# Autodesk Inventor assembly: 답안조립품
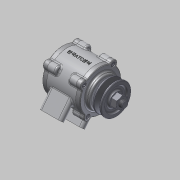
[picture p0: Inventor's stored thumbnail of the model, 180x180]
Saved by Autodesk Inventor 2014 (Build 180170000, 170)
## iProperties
Created: 2015-03
Part Number: 답안조립품
Document SubType Name: Assembly
Designer: MYHOME
Author: MYHOME
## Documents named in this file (11)
- C:\Documents and Settings\MYHOME\바탕 화면\450306V1023\답안조립품.iam
- C:\Documents and Settings\MYHOME\바탕 화면\450306V1023\본체.ipt
- C:\Documents and Settings\MYHOME\바탕 화면\450306V1023\커버2.ipt
- C:\Documents and Settings\MYHOME\바탕 화면\450306V1023\커버.ipt
- C:\Documents and Settings\MYHOME\바탕 화면\450306V1023\오일실.ipt
- C:\Documents and Settings\MYHOME\바탕 화면\450306V1023\M 4 x 12.ipt
- C:\Documents and Settings\MYHOME\바탕 화면\450306V1023\베어링 6204.ipt
- C:\Documents and Settings\MYHOME\바탕 화면\450306V1023\축.ipt
- C:\Documents and Settings\MYHOME\바탕 화면\450306V1023\키(4 x 4 x 12).ipt
- C:\Documents and Settings\MYHOME\바탕 화면\450306V1023\V벨트풀리.ipt
- C:\Documents and Settings\MYHOME\바탕 화면\450306V1023\너트 M12x1.25.ipt
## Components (14 placed, 6 different names)
1. KS B 2804 D D - 20 32 8:1
2. KS B 2023 6204 - 20 x 47 x 14:1 — 각도:1
3. KS B 2023 6204 - 20 x 47 x 14:2 — 각도:2
4. KS B 1311 (I) 4 x 4 x 12:1
5. 그루브 풀리1:1
6. KS B 1012 클래스 1 일반 - 미터 M12x1.25:1 — 각도:3
7. KS B 1003 - 미터 M 4 x 12:2
8. KS B 1003 - 미터 M 4 x 12:3
9. KS B 1003 - 미터 M 4 x 12:4
10. KS B 1003 - 미터 M 4 x 12:5
11. KS B 1003 - 미터 M 4 x 12:1
12. KS B 1003 - 미터 M 4 x 12:6
13. KS B 1003 - 미터 M 4 x 12:7
14. KS B 1003 - 미터 M 4 x 12:8
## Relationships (3: Angle 3)
- 각도:1 [Angle]: KS B 2023 6204 - 20 x 47 x 14:1
- 각도:2 [Angle]: KS B 2023 6204 - 20 x 47 x 14:2
- 각도:3 [Angle]: KS B 1012 클래스 1 일반 - 미터 M12x1.25:1
